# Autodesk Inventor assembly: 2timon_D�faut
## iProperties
Created: 2011-01
Part Number: 2timon_D�faut
Document SubType Name: Assembly
Designer: eric
Mass: 68.6923 g
Surface Area: 1295.09 cm^2
Volume: 68.6923 cm^3
Density: 1 g/cm^3
Author: eric
